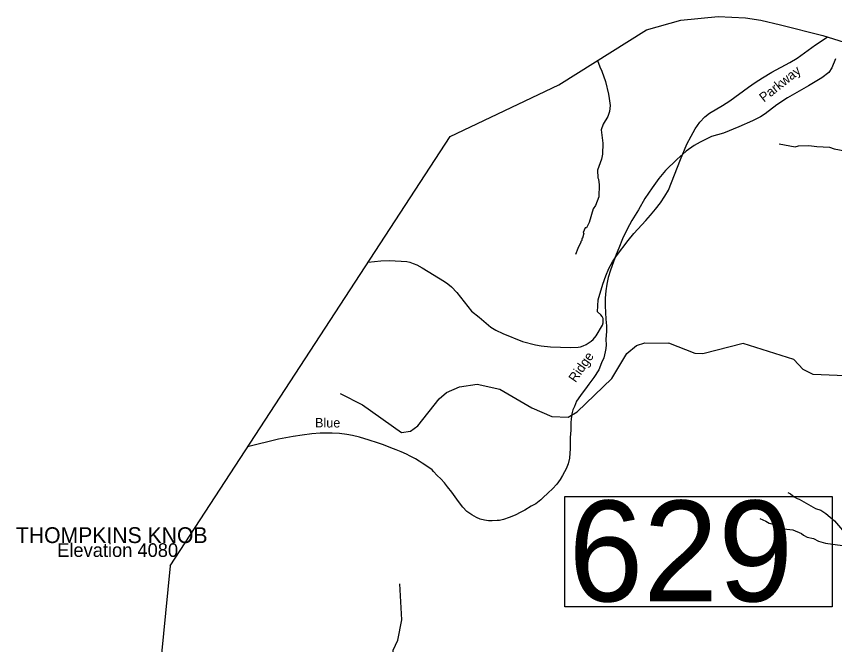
# Model space of a CAD drawing. Extents: x 1248224 to 1454986, y 825081 to 985870.
# Drawn here: x 1267334 to 1278711, y 914371 to 923109 of the extents above; entities that cross this region are included whole.
import ezdxf

# ---------------------------------------------------------------- set-up
doc = ezdxf.new("R2010")
doc.units = 0
for name, color, linetype in [('Exist Boundary Political CountyLine', 7, 'Continuous'), ('Exist Geographical Mountain Summit Elevation Number Label', 7, 'Continuous'), ('Exist Geographical Mountain Summit Label', 7, 'Continuous'), ('Exist Hydrographic Creek Single Shore', 7, 'Continuous'), ('Exist Hydrographic Misc Water Feature', 7, 'Continuous'), ('Exist Road Blue Ridge Parkway', 7, 'Continuous'), ('Exist Road Blue Ridge Parkway Label', 7, 'Continuous'), ('Exist Road Secondary Structure Standard Bridge Number Label', 7, 'Continuous')]:
    doc.layers.add(name, color=color, linetype=linetype)

msp = doc.modelspace()

# ---------------------------------------------------------------- linework, layer by layer
at = {"layer": 'Exist Boundary Political CountyLine'}
for points in [[(1269471, 915469), (1273366, 921437), (1274876, 922156), (1276093, 922922), (1276572, 923058), (1277093, 923109), (1277472, 923088), (1277686, 923054), (1277958, 922992), (1278547, 922843), (1279064, 922679)], [(1269471, 915469), (1269315, 913870)]]:
    msp.add_lwpolyline(points, dxfattribs=at)
at = {"layer": 'Exist Hydrographic Creek Single Shore'}
msp.add_lwpolyline([(1281684, 914925), (1281640, 914997), (1281672, 915288), (1281719, 915497), (1281710, 915813), (1281641, 916009), (1281616, 916057), (1281348, 916339), (1281086, 916544), (1281022, 916657), (1280915, 916708), (1280614, 917023), (1280177, 917209), (1279996, 917324), (1279858, 917468), (1279489, 917751), (1278856, 918109), (1278414, 918127), (1278274, 918199), (1278144, 918336), (1277441, 918561), (1276879, 918418), (1276770, 918420), (1276407, 918562)], dxfattribs=at)
at = {"layer": 'Exist Hydrographic Misc Water Feature'}
for points in [[(1272227, 919692), (1272401, 919709), (1272520, 919712), (1272763, 919698), (1272804, 919689), (1272850, 919674), (1272900, 919653), (1272976, 919613), (1273289, 919424), (1273334, 919391), (1273382, 919348), (1273457, 919267), (1273662, 919008), (1273771, 918925), (1273933, 918788), (1273999, 918746), (1274097, 918697), (1274369, 918587), (1274554, 918539), (1274631, 918525), (1274759, 918513), (1275040, 918504), (1275143, 918507), (1275179, 918513), (1275216, 918525), (1275257, 918545), (1275326, 918591), (1275356, 918617), (1275397, 918665), (1275485, 918815), (1275493, 918845), (1275495, 918876), (1275491, 918907), (1275479, 918934), (1275460, 918957), (1275412, 918998), (1275425, 919165), (1275488, 919384), (1275528, 919500), (1275572, 919601), (1275622, 919693), (1275680, 919780), (1275839, 919991), (1275918, 920087), (1276086, 920268), (1276152, 920344), (1276220, 920426), (1276291, 920518), (1276352, 920608), (1276401, 920692), (1276567, 921120), (1276658, 921333), (1276714, 921444), (1276773, 921543), (1276837, 921636), (1276904, 921712), (1276970, 921762), (1277151, 921868), (1277252, 921934), (1277515, 922125), (1277608, 922190), (1277706, 922254), (1277837, 922331), (1278089, 922469), (1278188, 922528), (1278444, 922711), (1278592, 922810), (1278611, 922819)], [(1275415, 922495), (1275445, 922408), (1275475, 922347), (1275524, 922202), (1275569, 922029), (1275576, 921968), (1275592, 921868), (1275581, 921784), (1275556, 921717), (1275495, 921612), (1275465, 921533), (1275487, 921344), (1275483, 921192), (1275471, 921124), (1275415, 920968), (1275419, 920863), (1275427, 920847), (1275437, 920767), (1275434, 920599), (1275387, 920480), (1275356, 920433), (1275296, 920244), (1275260, 920169), (1275244, 920169), (1275214, 920102), (1275226, 920094), (1275204, 920026), (1275196, 920018), (1275195, 919994), (1275183, 919979), (1275183, 919967), (1275139, 919882), (1275109, 919798)], [(1277940, 921338), (1278160, 921295), (1278208, 921309), (1278352, 921312), (1278464, 921297), (1278640, 921291), (1278703, 921269), (1278851, 921240)], [(1271836, 917865), (1272149, 917708), (1272691, 917320), (1272815, 917340), (1272918, 917413), (1273211, 917788), (1273313, 917878), (1273497, 917957), (1273741, 917994), (1274057, 917926), (1274501, 917667), (1274781, 917544), (1275006, 917536), (1275133, 917609), (1275611, 918072), (1275820, 918419), (1275956, 918531), (1276074, 918568), (1276407, 918562)], [(1278058, 916486), (1278098, 916468), (1278149, 916427), (1278192, 916403), (1278220, 916394), (1278447, 916266), (1278519, 916240), (1278590, 916194), (1278709, 916091), (1278818, 915962)], [(1277671, 916127), (1277754, 916089), (1277800, 916060), (1277907, 916033), (1277951, 916008), (1278006, 915984), (1278130, 915966), (1278248, 915919), (1278280, 915894), (1278331, 915866), (1278419, 915848), (1278488, 915811), (1278584, 915784), (1278819, 915748)], [(1272624, 914008), (1272553, 914095), (1272575, 914295), (1272637, 914435), (1272693, 914716), (1272664, 915219)]]:
    msp.add_lwpolyline(points, dxfattribs=at)
at = {"layer": 'Exist Road Blue Ridge Parkway'}
for points in [[(1278723, 922518), (1278670, 922392), (1278629, 922328), (1278535, 922254), (1278347, 922143), (1278054, 921976), (1277908, 921879), (1277747, 921755), (1277679, 921714), (1277571, 921656), (1277380, 921574), (1277166, 921486), (1277001, 921436), (1276840, 921360), (1276758, 921315), (1276645, 921233), (1276515, 921118), (1276360, 920967), (1276266, 920852), (1276173, 920723), (1276070, 920577), (1275982, 920418), (1275892, 920270), (1275825, 920149), (1275763, 920015), (1275709, 919883), (1275672, 919795), (1275636, 919696), (1275596, 919581), (1275564, 919477), (1275544, 919386), (1275530, 919293), (1275521, 919191), (1275521, 919084), (1275531, 918900), (1275540, 918804), (1275540, 918733), (1275531, 918615), (1275535, 918540), (1275528, 918489), (1275519, 918443), (1275501, 918359), (1275471, 918290), (1275432, 918195), (1275362, 918088), (1275293, 917993), (1275245, 917930), (1275185, 917852), (1275144, 917790), (1275123, 917758), (1275110, 917722), (1275093, 917685), (1275071, 917639), (1275059, 917580), (1275048, 917510), (1275043, 917454), (1275042, 917406), (1275041, 917352)], [(1272684, 917053), (1272617, 917081), (1272539, 917110), (1272438, 917150), (1272357, 917178), (1272238, 917214), (1272106, 917256), (1272008, 917281), (1271931, 917296), (1271829, 917310), (1271727, 917312), (1271638, 917312), (1271560, 917314), (1271442, 917302), (1271308, 917286), (1271183, 917268), (1270979, 917230), (1270550, 917121)], [(1275041, 917352), (1275035, 917252), (1275035, 917098), (1275024, 916965), (1275008, 916886), (1274978, 916816), (1274957, 916775), (1274928, 916722), (1274897, 916670), (1274847, 916603), (1274790, 916539), (1274730, 916481), (1274656, 916412), (1274625, 916384), (1274556, 916331), (1274493, 916298), (1274406, 916241), (1274348, 916216), (1274268, 916173), (1274186, 916140), (1274109, 916112), (1274051, 916099), (1274017, 916096), (1273951, 916091), (1273897, 916095), (1273845, 916102), (1273782, 916118), (1273733, 916140), (1273667, 916177), (1273598, 916225), (1273542, 916285), (1273482, 916361), (1273434, 916428), (1273388, 916492), (1273329, 916565), (1273285, 916620), (1273237, 916678), (1273185, 916725), (1273136, 916778), (1273117, 916801)], [(1273117, 916801), (1273040, 916854), (1272978, 916897), (1272935, 916922), (1272884, 916954), (1272810, 916994), (1272757, 917021), (1272684, 917053)]]:
    msp.add_lwpolyline(points, dxfattribs=at)
at = {"layer": 'Exist Road Secondary Structure Standard Bridge Number Label'}
msp.add_lwpolyline([(1274960, 916432), (1278676, 916432), (1278676, 914895), (1274960, 914895)], close=True, dxfattribs=at)

# ---------------------------------------------------------------- texts
at = {"layer": 'Exist Geographical Mountain Summit Elevation Number Label'}
msp.add_text('Elevation 4080', height=190, dxfattribs=at).set_placement((1267902, 915591))
at = {"layer": 'Exist Geographical Mountain Summit Label'}
msp.add_text('THOMPKINS KNOB', height=220, dxfattribs=at).set_placement((1267328, 915784))
at = {"layer": 'Exist Road Blue Ridge Parkway Label'}
for s, rotation, p in [('Parkway', 38.6839, (1277728, 921909)), ('Ridge', 55.328, (1275109, 918008))]:
    msp.add_text(s, height=131.2, rotation=rotation, dxfattribs=at).set_placement(p)
msp.add_text('Blue', height=131.2, dxfattribs=at).set_placement((1271487, 917392))
at = {"layer": 'Exist Road Secondary Structure Standard Bridge Number Label'}
msp.add_text('629', height=1400, dxfattribs=at).set_placement((1275010, 914974))

doc.saveas('drawing.dxf')
